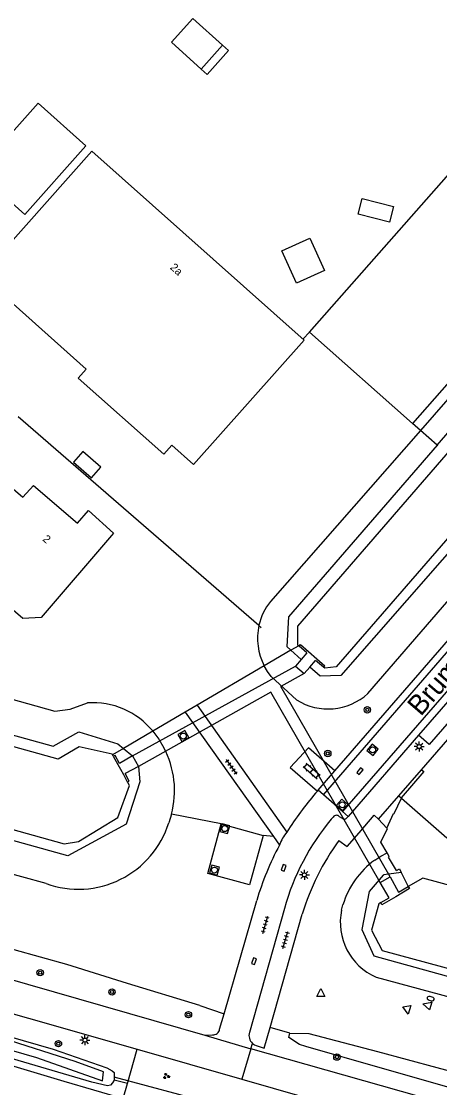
# Model space of a CAD drawing. Extents: x 128000 to 131008, y 398996 to 402500.
# Drawn here: x 128801.3 to 128853.6, y 399510.9 to 399644.1 of the extents above; entities that cross this region are included whole.
import ezdxf

# ---------------------------------------------------------------- set-up
doc = ezdxf.new("R2010")
doc.units = 0
for name, color, linetype in [('gg-afsc-hekwerk', 7, 'Continuous'), ('gg-afsc-muur', 7, 'Continuous'), ('gg-anno-huisnummerreeks BGT', 7, 'Continuous'), ('gg-anno-openbare ruimte label', 7, 'Continuous'), ('gg-bbg-gedigitaliseerde bijgebouw', 7, 'Continuous'), ('gg-bbg-hoofdgebouw', 7, 'Continuous'), ('gg-bbg-luifel en loopbrug', 7, 'Continuous'), ('gg-knt-BGT kruinlijn', 7, 'Continuous'), ('gg-knt-verharding', 7, 'Continuous'), ('gg-knt-verharding nz', 7, 'Continuous'), ('gg-kntw-beschoeiing', 7, 'Continuous'), ('gg-kntw-bovenkant insteek waterloop', 7, 'Continuous'), ('gg-kntw-midden sloot', 7, 'Continuous'), ('gg-kntw-waterlijn', 7, 'Continuous'), ('gg-kwrk-duiker nz buis', 7, 'Continuous'), ('gg-kwrk-duiker nz vlak', 7, 'Continuous'), ('gg-kwrk-kunstwerk', 7, 'Continuous'), ('gg-kwrk-uitstroombak niveau min 01', 7, 'Continuous'), ('gt-grn-groengrens', 7, 'Continuous'), ('gt-grn-vlakafsluiter', 7, 'Continuous'), ('gt-grn-weggrens', 7, 'Continuous'), ('gt-symb-boom', 7, 'Continuous'), ('gt-symb-brandkraan', 7, 'Continuous'), ('gt-symb-groenvak', 7, 'Continuous'), ('gt-symb-klinker verharding', 7, 'Continuous'), ('gt-symb-kolk', 7, 'Continuous'), ('gt-symb-lichtmast', 7, 'Continuous'), ('gt-symb-rioolschacht', 7, 'Continuous'), ('gt-symb-tegel verharding', 7, 'Continuous'), ('gt-symb-waterafsluiter', 7, 'Continuous')]:
    doc.layers.add(name, color=color, linetype=linetype)

# ---------------------------------------------------------------- blocks, each defined once
blk = doc.blocks.new('gt0-LMAST')
at = {"layer": 'gt-symb-lichtmast'}
for p, q in [((-0.18, 0.17), (-0.45, 0.44)), ((-0.01, 0.25), (-0.01, 0.62)), ((0.17, 0.17), (0.44, 0.44)), ((-0.26, 0), (-0.63, 0)), ((-0.18, -0.18), (-0.45, -0.45)), ((-0.01, -0.25), (-0.01, -0.63)), ((0.44, -0.45), (0.17, -0.18)), ((0.24, 0), (0.62, 0))]:
    blk.add_line(p, q, dxfattribs=at)
blk.add_circle((-0.01, 0), 0.25, dxfattribs=at)
blk = doc.blocks.new('gt0-BOOM')
at = {"layer": 'gt-symb-boom'}
for radius in [0.4, 0.2]:
    blk.add_circle((0, 0), radius, dxfattribs=at)
blk = doc.blocks.new('gt0-RS')
at = {"layer": 'gt-symb-rioolschacht'}
blk.add_lwpolyline([(-0.5, -0.5), (0.5, -0.5), (0.5, 0.5), (-0.5, 0.5)], close=True, dxfattribs=at)
blk.add_circle((0, 0), 0.375, dxfattribs=at)
blk = doc.blocks.new('gt0-WAFSL')
at = {"layer": 'gt-symb-waterafsluiter'}
for p, q in [((-0.5, -0.33), (0, 0.67)), ((0, 0.67), (0.5, -0.33)), ((0.5, -0.33), (-0.5, -0.33))]:
    blk.add_line(p, q, dxfattribs=at)
blk = doc.blocks.new('gt0-BR')
at = {"layer": 'gt-symb-brandkraan'}
for centre, radius, start, end in [((-0.24, 0), 0.206, 107.5669, 252.4331), ((0.6, -2.66), 3, 106.892, 107.5669), ((0, -0.69), 0.938, 73.108, 106.892), ((-0.6, -2.66), 3, 72.4331, 73.108), ((0.24, 0), 0.206, 287.567, 72.4331), ((0.6, 2.66), 3, 252.4331, 253.108), ((0, 0.69), 0.938, 253.108, 286.8921), ((-0.6, 2.66), 3, 286.8921, 287.567)]:
    blk.add_arc(centre, radius, start, end, dxfattribs=at)
blk = doc.blocks.new('gt0-KOLK')
at = {"layer": 'gt-symb-kolk'}
blk.add_lwpolyline([(0, 0), (0.38, 0), (0.38, 0.4), (-0.38, 0.4), (-0.38, 0), (0, 0)], dxfattribs=at)
blk = doc.blocks.new('gt0-TEG1')
at = {"layer": 'gt-symb-tegel verharding'}
for p, q in [((-1.13, 0), (1.12, 0)), ((-0.9, -0.25), (-0.9, 0.25)), ((-0.45, -0.25), (-0.45, 0.25)), ((0, -0.25), (0, 0.25)), ((0.45, -0.25), (0.45, 0.25)), ((0.9, -0.25), (0.9, 0.25))]:
    blk.add_line(p, q, dxfattribs=at)
blk = doc.blocks.new('gt0-KL1')
at = {"layer": 'gt-symb-klinker verharding'}
for p, q in [((-1.15, 0.3), (1.15, 0.3)), ((-1, -0.3), (-1, 0.3)), ((-0.5, 0.3), (-0.5, 0.45)), ((0, -0.3), (0, 0.3)), ((0.5, 0.3), (0.5, 0.45)), ((1, -0.3), (1, 0.3)), ((-1.15, -0.3), (1.15, -0.3)), ((-0.5, -0.45), (-0.5, -0.3)), ((0.5, -0.45), (0.5, -0.3))]:
    blk.add_line(p, q, dxfattribs=at)
blk = doc.blocks.new('gt0-GRVAK')
at = {"layer": 'gt-symb-groenvak'}
for p, q in [((-0.11, 0.19), (-0.23, 0.24)), ((-0.18, 0.15), (0.09, 0.15)), ((-0.09, 0.21), (-0.16, 0.32)), ((-0.05, 0.21), (-0.05, 0.39)), ((0, 0.21), (0.06, 0.32)), ((0.01, 0.19), (0.13, 0.24)), ((0.26, -0.05), (0.2, 0.06)), ((0.3, -0.05), (0.3, 0.13)), ((0.35, -0.05), (0.41, 0.06)), ((-0.25, -0.23), (-0.36, -0.18)), ((-0.32, -0.26), (-0.05, -0.26)), ((-0.23, -0.21), (-0.29, -0.1)), ((-0.18, -0.2), (-0.18, -0.02)), ((-0.14, -0.21), (-0.07, -0.1)), ((-0.12, -0.23), (0, -0.18)), ((0.24, -0.07), (0.12, -0.02)), ((0.17, -0.11), (0.44, -0.11)), ((0.37, -0.07), (0.49, -0.02))]:
    blk.add_line(p, q, dxfattribs=at)

msp = doc.modelspace()

# ---------------------------------------------------------------- linework, layer by layer
at = {"layer": 'gg-afsc-hekwerk'}
for p, q in [((128837.33, 399605.28), (128865.55, 399637.29)), ((128878.08, 399625.78), (128850.22, 399593.86)), ((128837.33, 399605.28), (128836.56, 399604.46)), ((128850.22, 399593.86), (128837.33, 399605.28)), ((128831.02, 399568.64), (128800.94, 399594.72)), ((128851.19, 399593.01), (128850.22, 399593.86)), ((128853.28, 399591.15), (128851.19, 399593.01)), ((128853.36, 399591.09), (128853.28, 399591.15)), ((128831.02, 399568.64), (128831.31, 399568.39)), ((128836, 399566.09), (128835.01, 399565.52)), ((128835.01, 399565.52), (128831.68, 399563.56)), ((128831.68, 399563.56), (128823.29, 399558.65)), ((128821.81, 399557.78), (128817.77, 399555.41)), ((128823.29, 399558.65), (128821.81, 399557.78)), ((128817.77, 399555.41), (128814.08, 399553.24)), ((128814.08, 399553.24), (128812.71, 399552.44))]:
    msp.add_line(p, q, dxfattribs=at)
at = {"layer": 'gg-afsc-muur'}
for points in [[(128846.98, 399543.29), (128847.84, 399545.14), (128847.93, 399545.11), (128848.85, 399547.02)], [(128847.02, 399540.21), (128846.24, 399541.53), (128847.08, 399543.23), (128846.98, 399543.29)], [(128848.19, 399537.99), (128847.21, 399539.68), (128847.3, 399539.75), (128847.02, 399540.21)]]:
    msp.add_lwpolyline(points, dxfattribs=at)
at = {"layer": 'gg-bbg-gedigitaliseerde bijgebouw'}
msp.add_line((128826.48, 399641.14), (128823.8, 399638.17), dxfattribs=at)
for points in [[(128823.8, 399638.17), (128820.08, 399641.52), (128822.76, 399644.49), (128826.48, 399641.14)], [(128809.39, 399628.58), (128803.41, 399633.9), (128795.76, 399625.31), (128801.74, 399619.99), (128809.39, 399628.58)], [(128843.93, 399621.98), (128847.82, 399620.97), (128847.32, 399619.04), (128843.43, 399620.04), (128843.93, 399621.98)], [(128839.19, 399613), (128835.69, 399611.42), (128833.88, 399615.43), (128837.38, 399617.01), (128839.19, 399613)]]:
    msp.add_lwpolyline(points, dxfattribs=at)
at = {"layer": 'gg-bbg-hoofdgebouw'}
for p, q in [((128851.32, 399550.6), (128854.61, 399554.38)), ((128848.78, 399547.08), (128848.85, 399547.02)), ((128848.85, 399547.02), (128854.5, 399542.1))]:
    msp.add_line(p, q, dxfattribs=at)
for points in [[(128796.29, 399612.35), (128809.42, 399600.67), (128808.42, 399599.55), (128819.14, 399590.03), (128820.13, 399591.15), (128822.83, 399588.75), (128836.67, 399604.29), (128810.13, 399627.91), (128796.29, 399612.35)], [(128799.99, 399585.93), (128801.51, 399584.64), (128802.83, 399586.13), (128808.35, 399581.41), (128809.72, 399582.98), (128812.84, 399580.17), (128803.78, 399569.63), (128801.5, 399569.48), (128790.94, 399578.52), (128793.73, 399581.71), (128795.26, 399580.4), (128799.99, 399585.93)], [(128851.32, 399550.6), (128851.63, 399550.36), (128848.78, 399547.08)]]:
    msp.add_lwpolyline(points, dxfattribs=at)
at = {"layer": 'gg-bbg-luifel en loopbrug'}
for points in [[(128823.8, 399638.17), (128824.54, 399637.5), (128827.22, 399640.47), (128826.48, 399641.14)], [(128807.82, 399589.02), (128810.08, 399587.06), (128811.26, 399588.42), (128809, 399590.38), (128807.82, 399589.02)]]:
    msp.add_lwpolyline(points, dxfattribs=at)
at = {"layer": 'gg-knt-BGT kruinlijn'}
for p, q in [((128889.87, 399637.11), (128851.19, 399593.01)), ((128844.63, 399560.12), (128901.57, 399626.21)), ((128851.19, 399593.01), (128832.44, 399571.64)), ((128804.43, 399536.36), (128673.13, 399572.64)), ((128820.07, 399545.02), (128819.75, 399543.97)), ((128841.34, 399533.05), (128841.51, 399533.71)), ((128845.66, 399524.68), (128964.93, 399492.26))]:
    msp.add_line(p, q, dxfattribs=at)
for points in [[(128776.33, 399566.07), (128805.49, 399557.92), (128807.44, 399558.15), (128809.58, 399558.94)], [(128835.71, 399559.33), (128832.56, 399562.23), (128832.08, 399562.87), (128831.68, 399563.56)], [(128817.77, 399555.41), (128818.49, 399554.41), (128819.11, 399553.34)], [(128845.48, 399539.29), (128846.23, 399539.79), (128847.02, 399540.21)]]:
    msp.add_lwpolyline(points, dxfattribs=at)
for centre, radius, start, end in [((128838.33, 399567.01), 7.49, 141.8294, 167.4043), ((128838.33, 399567.01), 7.49, 167.4027, 207.3965), ((128810.28, 399549.28), 9.68, 39.2579, 94.124), ((128839.65, 399565.58), 7.39, 237.7852, 312.3278), ((128809.18, 399547.98), 11.29, 344.8086, 28.3569), ((128808.44, 399547.5), 11.84, 250.166, 342.6616), ((128851.66, 399530.7), 10.58, 125.7183, 163.4515), ((128848.62, 399531.51), 7.44, 168.0467, 246.5364)]:
    msp.add_arc(centre, radius, start, end, dxfattribs=at)
at = {"layer": 'gg-knt-verharding'}
for p, q in [((128839.07, 399547.45), (128922.74, 399644.08)), ((128925.18, 399641.97), (128841.45, 399545.37)), ((128840.51, 399550.45), (128907.51, 399627.87)), ((128872.55, 399579.82), (128850.95, 399554.9)), ((128821.81, 399557.78), (128832.82, 399542.23)), ((128823.29, 399558.65), (128834.51, 399542.81)), ((128850.95, 399554.9), (128842.16, 399544.75)), ((128838.42, 399548.03), (128840.51, 399550.45)), ((128848.49, 399547.34), (128851.32, 399550.6)), ((128838.09, 399547.65), (128838.32, 399547.91)), ((128838.32, 399547.91), (128838.42, 399548.03)), ((128841.45, 399545.37), (128839.07, 399547.45)), ((128845.94, 399544.4), (128848.49, 399547.34)), ((128840.29, 399544.68), (128840.06, 399544.4)), ((128841.38, 399544.55), (128841.1, 399544.72)), ((128842.16, 399544.75), (128842.03, 399544.61)), ((128832.82, 399542.23), (128833.57, 399541.17)), ((128826.65, 399520.07), (128830.74, 399534.26)), ((128834.21, 399533.24), (128829.82, 399517.77)), ((128832.4, 399518.36), (128836.43, 399532.55)), ((128826.1, 399518.17), (128826.65, 399520.07)), ((128824.26, 399517.42), (128825.2, 399517.46)), ((128824.26, 399517.42), (128829.99, 399515.72)), ((128829.99, 399515.72), (128830.22, 399516.38)), ((128815.78, 399515.66), (128828.86, 399511.92)), ((128828.86, 399511.92), (128836.69, 399509.69))]:
    msp.add_line(p, q, dxfattribs=at)
for points in [[(128872.55, 399579.82), (128873.96, 399578.68), (128852.29, 399553.75), (128850.95, 399554.9)], [(128687.11, 399556.61), (128735.86, 399542.82), (128824.26, 399517.42)], [(128840.51, 399550.45), (128837.19, 399553.32), (128834.92, 399550.86), (128838.32, 399547.91)], [(128710.25, 399545.81), (128734.84, 399538.75), (128815.78, 399515.66)], [(128843.52, 399542.7), (128845.43, 399544.92), (128845.94, 399544.4)], [(128841.02, 399541.74), (128842.05, 399540.98), (128843.52, 399542.7)], [(128830.22, 399516.38), (128830.44, 399516.23), (128830.68, 399516.11), (128831.67, 399515.81), (128832.4, 399518.36)], [(128961.54, 399478.33), (128954.59, 399480.44), (128829.99, 399515.72)]]:
    msp.add_lwpolyline(points, dxfattribs=at)
for centre, radius, start, end in [((128866.73, 399522.76), 37.94, 138.9941, 148.0993), ((128862.51, 399525.52), 29.34, 139.9329, 164.728), ((128840.71, 399544.37), 0.526, 42.3767, 143.1365), ((128841.68, 399544.83), 0.413, 223.1268, 327.4209), ((128865.88, 399523.59), 30.79, 143.8649, 163.0698), ((128866.42, 399523.68), 37.21, 151.976, 163.4859), ((128825.3, 399518.26), 0.806, 263.0941, 353.5689), ((128831.13, 399517.4), 1.36, 164.0031, 228.0405)]:
    msp.add_arc(centre, radius, start, end, dxfattribs=at)
at = {"layer": 'gg-knt-verharding nz'}
msp.add_arc((128839.73, 399538.71), 6.64, 141.8471, 158.2581, dxfattribs=at)
at = {"layer": 'gg-kntw-beschoeiing'}
for p, q in [((128836.05, 399566.05), (128836, 399566.09)), ((128812.79, 399552.29), (128812.71, 399552.44))]:
    msp.add_line(p, q, dxfattribs=at)
for points in [[(128892.54, 399634.03), (128835.82, 399568.52), (128835.84, 399566.22), (128836, 399566.09)], [(128898.48, 399632.43), (128898.07, 399629.59), (128840.68, 399563.47), (128839.23, 399563.28), (128839.1, 399563.4)], [(128672.28, 399582.04), (128672.17, 399581.71), (128674.24, 399578.31), (128806.68, 399541.32), (128808.45, 399541.64), (128813.38, 399544.62), (128814.84, 399548.64), (128814.59, 399549.09)], [(128812.71, 399552.44), (128812.65, 399552.54), (128808.54, 399553.47), (128805.91, 399551.93), (128772.22, 399561.29)], [(128958.28, 399508.13), (128851.48, 399537.06), (128849.65, 399535.99)], [(128846.25, 399533.99), (128846.01, 399533.84), (128845.07, 399530.54), (128846.41, 399528.01), (128886.11, 399517.27)]]:
    msp.add_lwpolyline(points, dxfattribs=at)
at = {"layer": 'gg-kntw-bovenkant insteek waterloop'}
msp.add_line((128836.29, 399564.38), (128835.01, 399565.52), dxfattribs=at)
for points in [[(128853.28, 399591.15), (128891.14, 399634.86), (128892.48, 399635.34)], [(128898.51, 399634.38), (128899.75, 399633.46), (128899.86, 399629.28), (128841.27, 399562.37), (128838.67, 399562.27), (128837.37, 399563.42)], [(128853.28, 399591.15), (128834.71, 399569.71), (128834.48, 399565.99), (128835.01, 399565.52)], [(128712.24, 399542.65), (128744.27, 399533.16), (128776.12, 399524.1), (128805.29, 399515.67), (128812.02, 399513.32), (128812.67, 399512.98), (128812.91, 399512.76), (128812.91, 399511.81)], [(128812.91, 399511.81), (128812.71, 399511.46), (128812.45, 399511.17), (128812.07, 399511.08), (128810.15, 399511.54), (128781.04, 399520.07), (128747.04, 399530.09), (128724.01, 399537.18)], [(128962.2, 399481.42), (128960.3, 399481.38), (128943.16, 399486.67), (128921.16, 399492.73), (128896.77, 399499.11), (128871.13, 399506.22), (128846.15, 399513.32), (128836.88, 399516.01), (128836.07, 399516.27), (128834.77, 399517.14), (128834.86, 399517.66)], [(128834.86, 399517.66), (128837.23, 399517.64), (128845.85, 399515.38), (128856.97, 399512.37), (128871.9, 399507.87), (128898.11, 399500.57), (128921.71, 399493.89), (128945.61, 399487.82), (128955.51, 399484.87)]]:
    msp.add_lwpolyline(points, dxfattribs=at)
at = {"layer": 'gg-kntw-midden sloot'}
msp.add_lwpolyline([(128823.62, 399521.11), (128814.58, 399523.86), (128806.99, 399526.26), (128790.5, 399530.84), (128770.07, 399536.65), (128752.17, 399541.19), (128734.74, 399546.24), (128725.18, 399549.21), (128721.73, 399550.16), (128720.66, 399550.27), (128713.93, 399552.52), (128702.77, 399555.9), (128691.1, 399559.74), (128686.57, 399561.18), (128677.52, 399564.17), (128673.75, 399565.46), (128671.03, 399566.25)], dxfattribs=at)
at = {"layer": 'gg-kntw-waterlijn'}
msp.add_lwpolyline([(128811.57, 399512.83), (128808.05, 399514.11), (128798.94, 399517.04), (128770.48, 399525.18), (128713.36, 399541.85), (128711.54, 399542.18), (128711.35, 399541.45), (128724.5, 399537.68), (128745.07, 399531.51), (128778.6, 399521.77), (128803.22, 399514.61), (128811.45, 399511.7), (128811.57, 399512.83)], dxfattribs=at)
at = {"layer": 'gg-kwrk-duiker nz buis'}
msp.add_line((128832.73, 399506.88), (128812.91, 399512.18), dxfattribs=at)
at = {"layer": 'gg-kwrk-duiker nz vlak'}
for p, q in [((128815.22, 399552.32), (128835.58, 399563.54)), ((128836.68, 399562.62), (128833.77, 399560.99)), ((128847.43, 399537.21), (128833.77, 399560.99)), ((128832.5, 399560.28), (128815.95, 399550.99)), ((128846.17, 399536.49), (128832.5, 399560.28))]:
    msp.add_line(p, q, dxfattribs=at)
at = {"layer": 'gg-kwrk-kunstwerk'}
msp.add_line((128826.31, 399543.83), (128831.54, 399542.39), dxfattribs=at)
msp.add_lwpolyline([(128831.54, 399542.39), (128829.84, 399536.19), (128824.62, 399537.61), (128826.31, 399543.83)], dxfattribs=at)
at = {"layer": 'gg-kwrk-uitstroombak niveau min 01'}
for p, q in [((128837, 399565.21), (128836.05, 399566.05)), ((128836.29, 399564.38), (128835.58, 399563.54)), ((128837, 399565.21), (128836.29, 399564.38)), ((128835.58, 399563.54), (128836.68, 399562.62)), ((128836.68, 399562.62), (128837.37, 399563.42)), ((128837.37, 399563.42), (128838.1, 399564.26)), ((128839.1, 399563.4), (128838.1, 399564.26)), ((128812.79, 399552.29), (128813.37, 399551.26)), ((128815.22, 399552.32), (128815.95, 399550.99)), ((128813.37, 399551.26), (128813.7, 399550.67)), ((128815.95, 399550.99), (128814.29, 399550.11)), ((128813.7, 399550.67), (128814.08, 399550)), ((128846.17, 399536.49), (128847.43, 399537.21)), ((128847.27, 399534.58), (128846.17, 399536.49)), ((128847.43, 399537.21), (128848.47, 399535.29)), ((128848.47, 399535.29), (128849.65, 399535.99)), ((128846.25, 399533.99), (128847.27, 399534.58))]:
    msp.add_line(p, q, dxfattribs=at)
for points in [[(128836.05, 399566.05), (128836.2, 399566.25), (128839.25, 399563.6), (128839.1, 399563.4)], [(128815.22, 399552.32), (128813.59, 399551.39), (128813.03, 399552.39), (128812.79, 399552.29)], [(128814.08, 399550), (128814.56, 399549.08), (128814.59, 399549.09)], [(128814.59, 399549.09), (128814.81, 399549.18), (128814.29, 399550.11)], [(128849.65, 399535.99), (128849.85, 399535.74), (128848.11, 399534.72)], [(128848.11, 399534.72), (128846.36, 399533.7), (128846.25, 399533.99)]]:
    msp.add_lwpolyline(points, dxfattribs=at)
at = {"layer": 'gt-grn-groengrens'}
for p, q in [((128814.08, 399553.24), (128815.22, 399552.32)), ((128826.31, 399543.83), (128820.07, 399545.02)), ((128845.94, 399544.4), (128846.98, 399543.29)), ((128832.82, 399542.23), (128831.54, 399542.39)), ((128823.62, 399521.11), (128826.65, 399520.07)), ((128834.86, 399517.66), (128832.4, 399518.36)), ((128814.58, 399511.36), (128815.78, 399515.66)), ((128814.58, 399511.36), (128812.91, 399511.81))]:
    msp.add_line(p, q, dxfattribs=at)
for points in [[(128815.95, 399550.99), (128816.11, 399549.1), (128814.43, 399543.78), (128807.13, 399539.82), (128672.62, 399577.25), (128670.34, 399581.21), (128670.72, 399583.82)], [(128773.2, 399562.42), (128805.3, 399553.52), (128808.5, 399555.34), (128813.37, 399553.82), (128814.08, 399553.24)], [(128848.78, 399537.76), (128846.62, 399537.47), (128846.56, 399537.41)], [(128723.82, 399536.5), (128806.65, 399511.69), (128814.06, 399509.51), (128814.58, 399511.36)], [(128846.56, 399537.41), (128844.8, 399535.37), (128843.87, 399530.63), (128845.39, 399527.35), (128882.73, 399516.99), (128886.98, 399515.84)]]:
    msp.add_lwpolyline(points, dxfattribs=at)
at = {"layer": 'gt-grn-vlakafsluiter'}
for p, q in [((128848.49, 399547.34), (128848.78, 399547.08)), ((128848.78, 399537.76), (128849.65, 399535.99))]:
    msp.add_line(p, q, dxfattribs=at)
msp.add_lwpolyline([(128848.19, 399537.99), (128848.57, 399538.21), (128848.78, 399537.76)], dxfattribs=at)
at = {"layer": 'gt-grn-weggrens'}
for p, q in [((128839.07, 399547.45), (128838.42, 399548.03)), ((128841.45, 399545.37), (128842.16, 399544.75)), ((128829.99, 399515.72), (128828.86, 399511.92))]:
    msp.add_line(p, q, dxfattribs=at)

# ---------------------------------------------------------------- block references
at = {"layer": 'gt-symb-boom'}
for p in [(128844.56, 399558.08), (128839.62, 399552.62), (128803.67, 399525.23), (128812.65, 399522.81), (128822.2, 399519.98), (128805.95, 399516.36), (128840.76, 399514.68)]:
    msp.add_blockref('gt0-BOOM', p, dxfattribs=at)
at = {"layer": 'gt-symb-brandkraan', "rotation": -15.189787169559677}
msp.add_blockref('gt0-BR', (128852.47, 399521.99), dxfattribs=at)
at = {"layer": 'gt-symb-groenvak'}
msp.add_blockref('gt0-GRVAK', (128819.43, 399512.3), dxfattribs=at)
at = {"layer": 'gt-symb-klinker verharding', "rotation": -40.98653320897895}
msp.add_blockref('gt0-KL1', (128837.6, 399550.45), dxfattribs=at)
at = {"layer": 'gt-symb-kolk'}
for p, rotation in [((128843.78, 399550.29), 50.19442890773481), ((128834.28, 399538.27), 70.00710602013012), ((128830.6, 399526.59), 70.00710602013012)]:
    msp.add_blockref('gt0-KOLK', p, dxfattribs=dict(at, rotation=rotation))
at = {"layer": 'gt-symb-lichtmast'}
for p in [(128851.05, 399553.49), (128836.7, 399537.45), (128809.28, 399516.8)]:
    msp.add_blockref('gt0-LMAST', p, dxfattribs=at)
at = {"layer": 'gt-symb-rioolschacht'}
for p, rotation in [((128821.56, 399554.8), 29.87282104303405), ((128845.22, 399553.08), 50.59775872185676), ((128841.42, 399546.21), 48.0000087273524), ((128826.75, 399543.23), 74.81021283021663), ((128825.46, 399538.05), 74.81021283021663)]:
    msp.add_blockref('gt0-RS', p, dxfattribs=dict(at, rotation=rotation))
at = {"layer": 'gt-symb-tegel verharding'}
for p, rotation in [((128827.58, 399550.94), -54.52896067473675), ((128831.81, 399531.23), 73.92082762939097), ((128834.33, 399529.32), 73.9208276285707)]:
    msp.add_blockref('gt0-TEG1', p, dxfattribs=dict(at, rotation=rotation))
at = {"layer": 'gt-symb-waterafsluiter'}
msp.add_blockref('gt0-WAFSL', (128838.77, 399522.6), dxfattribs=at)
for p, rotation in [((128852.16, 399521.16), 74.10181291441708), ((128849.55, 399520.72), -170.38697413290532)]:
    msp.add_blockref('gt0-WAFSL', p, dxfattribs=dict(at, rotation=rotation))

# ---------------------------------------------------------------- texts
at = {"layer": 'gg-anno-huisnummerreeks BGT'}
for s, rotation, p in [('2a', 318.3, (128819.83, 399613.26)), ('2', 319.5, (128803.9, 399579.29))]:
    msp.add_text(s, height=1, rotation=rotation, dxfattribs=at).set_placement(p)
at = {"layer": 'gg-anno-openbare ruimte label'}
msp.add_text('Brummenweg', height=2.5, rotation=49.2, dxfattribs=at).set_placement((128851.24, 399557.18))

doc.saveas('drawing.dxf')
